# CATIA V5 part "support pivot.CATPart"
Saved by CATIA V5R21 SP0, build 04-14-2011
Part number: SupportPivot
Bounding box of the stored display mesh (mm): x -21 to 21, y -21 to 38, z 0 to 27
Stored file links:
  C:\Users\2027.DESARCY-LEMIE30\Desktop\V15(20.03.2023)\support pivot.CATPart
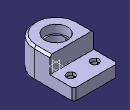
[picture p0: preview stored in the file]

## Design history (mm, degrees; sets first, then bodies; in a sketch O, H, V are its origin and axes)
Body1 (main body)
  Sketch1 on xy-plane, origin (0, 0, 0), H (1, 0, 0), V (0, 1, 0)
    arc A1 centre (0, 0) radius 21 from (-21, 0) to (21, 0) ccw
    line L1 (-21, 15) -> (21, 15)
    line L2 (21, 15) -> (21, 0)
    line L3 (-21, 0) -> (-21, 15)
    radius A1 = 21
    length L1 = 42
    distance L1 H = 15
    horizontal: L1 H
    vertical: L2 V, L3 V
  Pad1: profile Sketch1, direction (0, 0, 1), length 27
  Sketch2 on xy-plane, origin (0, 0, 0), H (1, 0, 0), V (0, 1, 0)
    line L1 (21, 0) -> (21, 38)
    line L2 (21, 38) -> (-21, 38)
    line L3 (-21, 38) -> (-21, 0)
    line L4 (-21, 0) -> (21, 0)
    distance L2 H = 38
    distance L1 V = 21
    length L2 = 42
    horizontal: L2 H, L4 H
    vertical: L1 V, L3 V
  Pad2: profile Sketch2, direction (0, 0, 1), length 11
  Sketch3 on end face of Pad1, origin (1.3571, -8.2844, 27), H (1, 0, 0), V (0, 1, 0)
    point P1 (-1.3571, 8.2844)
    reference projected arc E1 centre (-1.3571, 8.2844) radius 21 from (-22.3571, 8.2844) to (19.6429, 8.2844) ccw from edge [face of Pad1 from Sketch1.A1 | end face of Pad1]
    reference intersected line E2 through (-1.3571, 0) direction (0, 1) from yz-plane
    reference intersected line E3 through (0, 8.2844) direction (-1, 0) from zx-plane
    radius E1 = 21 (reference)
    distance P1 E2 = 0
    distance E3 P1 = 0
  Hole1: placed by Sketch3, at (0, 0, 27) direction (0, 0, -1), diameter 22, through (limit type 6)
  Sketch4 on face of Pad2, origin (-11.5216, 25.6596, 0), H (1, 0, 0), V (0, -1, 0)
    point P1 (0.0216, 0.1596)
    reference projected line E1 (-9.4784, 10.6596) -> (-9.4784, 25.6596) from edge [face of Pad2 | face of Pad2]
    reference projected line E2 (32.5216, -12.3404) -> (-9.4784, -12.3404) from edge [start face of Pad2 | face of Pad2 from Sketch2.L2]
    distance P1 E1 = 9.5
    distance P1 E2 = 12.5
  Hole2: placed by Sketch4, at (-11.5, 25.5, 0) direction (0, 0, 1), diameter 7.9, through (limit type 6), counterbore diameter 12.76, counterbore depth 8
  Sketch5 on face of Pad2, origin (12.0454, 25.2497, 0), H (1, 0, 0), V (0, -1, 0)
    point P1 (-0.5454, -0.2503)
    reference projected line E1 (8.9546, 25.2497) -> (8.9546, 10.2497) from edge [face of Pad2 | face of Pad2]
    reference projected line E2 (8.9546, -12.7503) -> (-33.0454, -12.7503) from edge [start face of Pad2 | face of Pad2 from Sketch2.L2]
    distance P1 E1 = 9.5
    distance P1 E2 = 12.5
  Hole3: placed by Sketch5, at (11.5, 25.5, 0) direction (0, 0, 1), diameter 7.9, through (limit type 6), counterbore diameter 12.76, counterbore depth 8
  Chamfer1: length 2, angle 45, on edge [face of Pad2 from Sketch2.L2 | face of Pad2]
  Chamfer2: length 2, angle 45, on edge [face of Pad1 from Sketch1.A1 | end face of Pad1]
  Chamfer3: length 2, angle 45, on edge [face of Pad2 | face of Pad2 from Sketch2.L2]
  Sketch6 on xy-plane, origin (0, 0, 0), H (1, 0, 0), V (0, 1, 0)
    circle A1 centre (0, 0) radius 9.5
    projected circle E1 centre (0, 0) radius 11 from edge [end face of Pad1 | face of Hole1]
    radius A1 = 9.5
  Pad3: profile Sketch6, direction (0, 0, 1), length 19, opposite side length -7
